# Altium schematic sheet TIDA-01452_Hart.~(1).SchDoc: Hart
size 431 x 279 mm; Date: Not shown in title block; ApprovedBy: Not shown in title block; CheckedBy: Not shown in title block; Author: Not shown in title block; CompanyName: Not shown in title block; DrawnBy: Il Han Kim; Engineer: Not shown in title block; Organization: Not shown in title block; Address1: Not shown in title block; Address2: Not shown in title block; Address3: Not shown in title block; Address4: Not shown in title block; DocumentNumber: 6; Revision: Use project parameter SCH_Rev; SheetNumber: 8; SheetTotal: 12; PageSetup: Record=PageOptions¦CenterHorizontal=True¦CenterVertical=True¦PrintScale=0.64¦XCorrection=1.00¦YCorrection=1.00¦PrintKind=0¦BorderSize=5000000¦LeftOffset=0¦BottomOffset=0¦Orientation=2¦PaperLength=1000¦PaperWidth=1000¦Scale=100¦PaperSource=15¦PrintQuality=600¦MediaType=1¦DitherType=10¦PrintScaleMode=1¦PaperKind=Letter
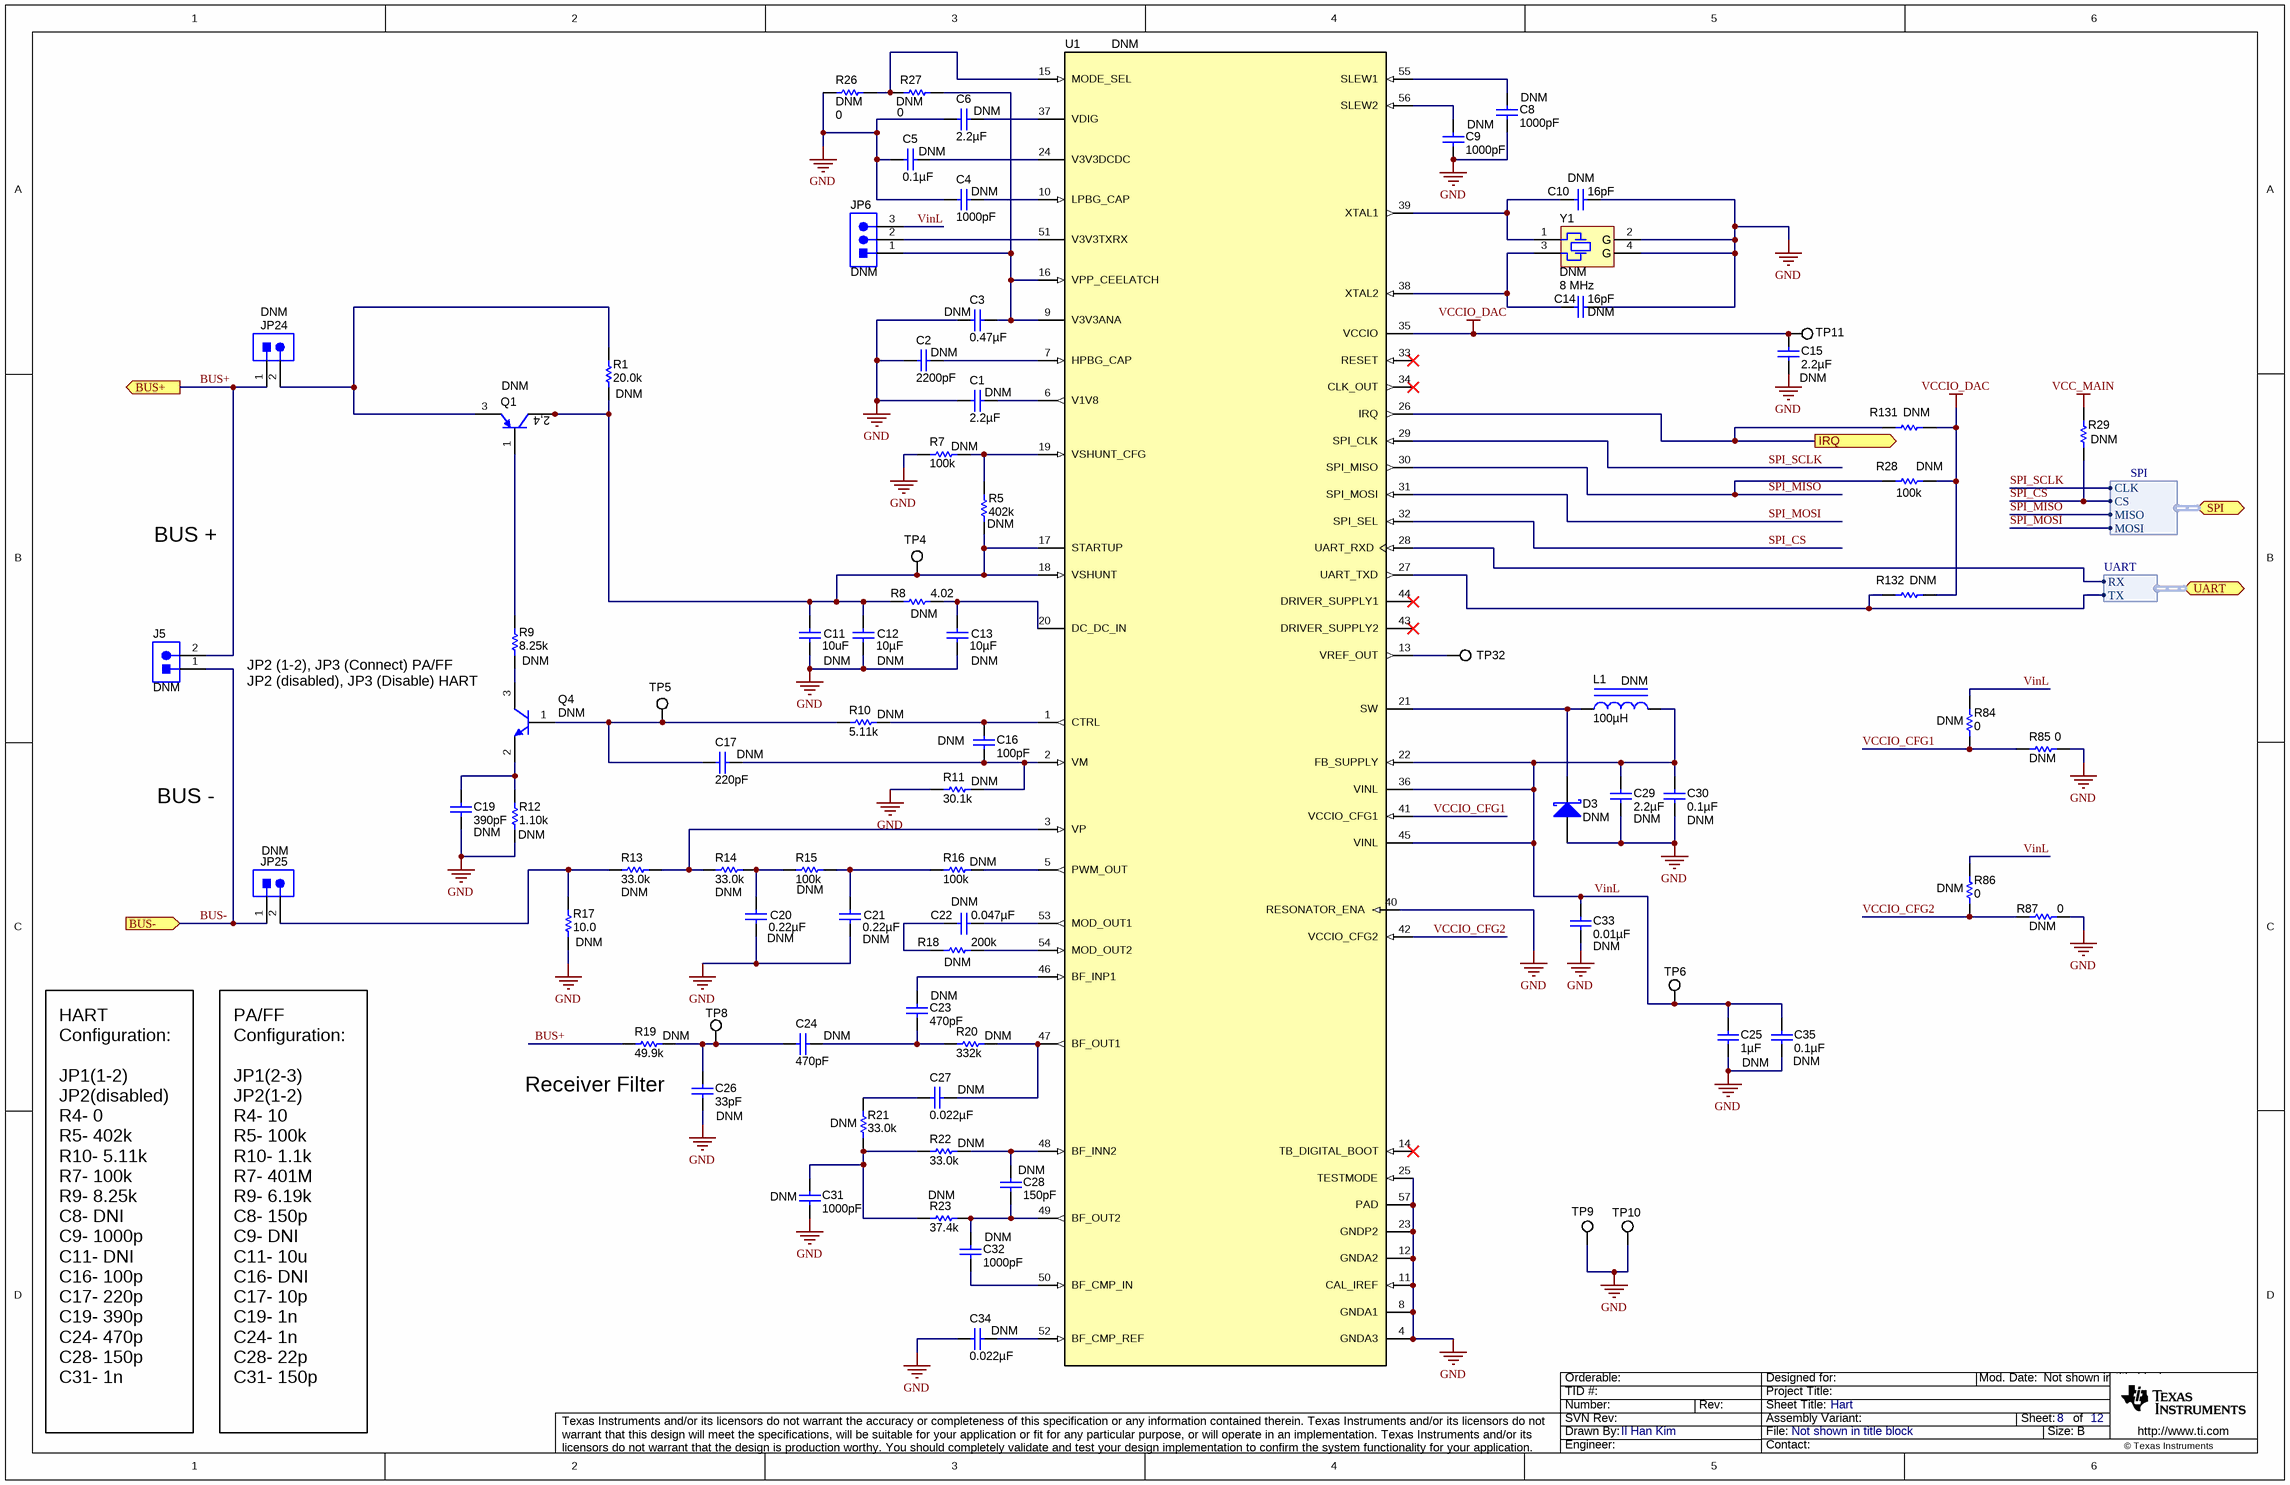
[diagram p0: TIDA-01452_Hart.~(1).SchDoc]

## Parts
C1  DNM  ValueDisplayed: 2.2µF  [0402]
C2  DNM  ValueDisplayed: 2200pF  [0402]
C3  DNM  ValueDisplayed: 0.47µF  [0402]
C4  DNM  ValueDisplayed: 1000pF  [0402]
C5  DNM  ValueDisplayed: 0.1µF  [0402]
C6  DNM  ValueDisplayed: 2.2µF  [0402]
C8  DNM  ValueDisplayed: 1000pF  [0402]
C9  DNM  ValueDisplayed: 1000pF  [0402]
C10  DNM  ValueDisplayed: 16pF  [0402]
C11  DNM  ValueDisplayed: 10uF  [1206_190]
C12  DNM  ValueDisplayed: 10µF  [1206_190]
C13  DNM  ValueDisplayed: 10µF  [1206_190]
C14  DNM  ValueDisplayed: 16pF  [0402]
C15  DNM  ValueDisplayed: 2.2µF  [0805_HV]
C16  DNM  ValueDisplayed: 100pF  [0402]
C17  DNM  ValueDisplayed: 220pF  [0402]
C19  DNM  ValueDisplayed: 390pF  [0402]
C20  DNM  ValueDisplayed: 0.22µF  [0603]
C21  DNM  ValueDisplayed: 0.22µF  [0603]
C22  DNM  ValueDisplayed: 0.047µF  [0402]
C23  DNM  ValueDisplayed: 470pF  [0402]
C24  DNM  ValueDisplayed: 470pF  [0402]
C25  DNM  ValueDisplayed: 1µF  [0402]
C26  DNM  ValueDisplayed: 33pF  [0402]
C27  DNM  ValueDisplayed: 0.022µF  [0402]
C28  DNM  ValueDisplayed: 150pF  [0402]
C29  DNM  ValueDisplayed: 2.2µF  [0805_HV]
C30  DNM  ValueDisplayed: 0.1µF  [0402]
C31  DNM  ValueDisplayed: 1000pF  [0402]
C32  DNM  ValueDisplayed: 1000pF  [0402]
C33  DNM  ValueDisplayed: 0.01µF  [0402]
C34  DNM  ValueDisplayed: 0.022µF  [0402]
C35  DNM  ValueDisplayed: 0.1µF  [0402]
D3  DNM  [sod-323]
J5  DNM  [TERM_BLK_ED555-2DS]
JP6  DNM  [CONN_TMM-103-01-T-S]
JP24  DNM  [CONN_TMM-102-01-T-S]
JP25  DNM  [CONN_TMM-102-01-T-S]
L1  DNM  ValueDisplayed: 100µH  [CBC3225]
Q1  DNM  [SOT-89-3]
Q4  DNM  [SOT-23]
R1  DNM  ValueDisplayed: 20.0k  [0603]
R5  DNM  ValueDisplayed: 402k  [0402]
R7  DNM  ValueDisplayed: 100k  [0402]
R8  DNM  ValueDisplayed: 4.02  [0603]
R9  DNM  ValueDisplayed: 8.25k  [0603]
R10  DNM  ValueDisplayed: 5.11k  [0402]
R11  DNM  ValueDisplayed: 30.1k  [0402]
R12  DNM  ValueDisplayed: 1.10k  [0603]
R13  DNM  ValueDisplayed: 33.0k  [0402]
R14  DNM  ValueDisplayed: 33.0k  [0402]
R15  DNM  ValueDisplayed: 100k  [0402]
R16  DNM  ValueDisplayed: 100k  [0402]
R17  DNM  ValueDisplayed: 10.0  [0603]
R18  DNM  ValueDisplayed: 200k  [0402]
R19  DNM  ValueDisplayed: 49.9k  [0402]
R20  DNM  ValueDisplayed: 332k  [0402]
R21  DNM  ValueDisplayed: 33.0k  [0402]
R22  DNM  ValueDisplayed: 33.0k  [0402]
R23  DNM  ValueDisplayed: 37.4k  [0402]
R26  DNM  ValueDisplayed: 0  [0402]
R27  DNM  ValueDisplayed: 0  [0402]
R28  DNM  ValueDisplayed: 100k  [0402]
R29  DNM  [0402]
R84  DNM  value 0  [0402]
R85  DNM  value 0  [0402]
R86  DNM  value 0  [0402]
R87  DNM  ValueDisplayed: 0  [0402]
R131  DNM  [0402]
R132  DNM  [0402]
TP4  NA  [TPS0.8]  (value not drawn)  (no BOM)
TP5  NA  [TPS0.8]  (value not drawn)  (no BOM)
TP6  NA  [TPS0.8]  (value not drawn)  (no BOM)
TP8  NA  [TPS0.8]  (value not drawn)  (no BOM)
TP9  NA  [TPS0.8]  (value not drawn)  (no BOM)
TP10  NA  [TPS0.8]  (value not drawn)  (no BOM)
TP11  NA  [TPS0.8]  (value not drawn)  (no BOM)
TP32  NA  [TPS0.8]  (value not drawn)  (no BOM)
U1  DNM  [DAC8730]
Y1  DNM  Frequency: 8 MHz  [XTL14S]

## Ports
BUS+ (out), BUS- (in), IRQ (out), SPI (harness SPI), UART (harness UART)

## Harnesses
SPI: CLK, CS, MISO, MOSI
UART: RX, TX

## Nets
GND: C1.2 C2.2 C3.2 C4.2 C5.2 C6.2 C8.2 C9.2 C10.1 C11.2 C12.2 C13.2 C14.1 C15.1 C19.2 C20.2 C21.2 C25.2 C26.2 C29.2 C30.2 C31.2 C33.2 C34.2 C35.2 D3.2(A) R7.2 R11.1 R12.2 R17.1 R26.2 R85.2 R87.1 TP9.1 TP10.1 U1.4(GNDA3) U1.8(GNDA1) U1.11(CAL_IREF) U1.12(GNDA2) U1.23(GNDP2) U1.25(TESTMODE) U1.40(RESONATOR_ENA) U1.57(PAD) Y1.2(GND) Y1.4(GND)
VCC_MAIN: R29.1
VCCIO_DAC: C15.2 R28.1 R131.1 R132.1 TP11.1 U1.35(VCCIO)
BUS+: J5.2 JP24.1 R19.1 ; port BUS+
BUS-: J5.1 JP25.1 ; port BUS-
IRQ: R131.2 U1.26(IRQ) ; port IRQ
SPI_CS: R29.2 U1.32(SPI_SEL) ; port SPI.CS
SPI_MISO: R28.2 U1.30(SPI_MISO) ; port SPI.MISO
SPI_MOSI: U1.31(SPI_MOSI) ; port SPI.MOSI
SPI_SCLK: U1.29(SPI_CLK) ; port SPI.CLK
VCCIO_CFG1: R84.1 R85.1 U1.41(VCCIO_CFG1)
VCCIO_CFG2: R86.1 R87.2 U1.42(VCCIO_CFG2)
VinL: C25.1 C29.1 C30.1 C33.1 C35.1 JP6.3 L1.2 R84.2 R86.2 TP6.1 U1.22(FB_SUPPLY) U1.36(VINL) U1.45(VINL)
NetC1_1: C1.1 U1.6(V1V8)
NetC2_1: C2.1 U1.7(HPBG_CAP)
NetC3_1: C3.1 JP6.1 R27.1 U1.9(V3V3ANA) U1.16(VPP_CEELATCH)
NetC4_1: C4.1 U1.10(LPBG_CAP)
NetC5_1: C5.1 U1.24(V3V3DCDC)
NetC6_1: C6.1 U1.37(VDIG)
NetC8_1: C8.1 U1.55(SLEW1)
NetC9_1: C9.1 U1.56(SLEW2)
NetC10_2: C10.2 U1.39(XTAL1) Y1.1
NetC11_1: C11.1 C12.1 Q1.2(C) Q1.4(C) R1.1 R5.1 R8.1 TP4.1 U1.17(STARTUP) U1.18(VSHUNT)
NetC13_1: C13.1 R8.2 U1.20(DC_DC_IN)
NetC14_2: C14.2 U1.38(XTAL2) Y1.3
NetC16_1: C16.1 R10.2 U1.1(CTRL)
NetC16_2: C16.2 C17.1 R11.2 U1.2(VM)
NetC17_2: C17.2 Q4.1(B) R10.1 TP5.1
NetC19_1: C19.1 Q4.2(E) R12.1
NetC20_1: C20.1 R14.2 R15.1
NetC21_1: C21.1 R15.2 R16.1
NetC22_1: C22.1 U1.53(MOD_OUT1)
NetC22_2: C22.2 R18.1
NetC23_1: C23.1 U1.46(BF_INP1)
NetC23_2: C23.2 C24.1 R20.1
NetC24_2: C24.2 C26.1 R19.2 TP8.1
NetC27_1: C27.1 R20.2 U1.47(BF_OUT1)
NetC27_2: C27.2 R21.2
NetC28_1: C28.1 R22.2 U1.48(BF_INN2)
NetC28_2: C28.2 C32.1 R23.2 U1.49(BF_OUT2)
NetC31_1: C31.1 R21.1 R22.1 R23.1
NetC32_2: C32.2 U1.50(BF_CMP_IN)
NetC34_1: C34.1 U1.52(BF_CMP_REF)
NetD3_1: D3.1(K) L1.1 U1.21(SW)
NetJP6_2: JP6.2 U1.51(V3V3TXRX)
NetJP24_2: JP24.2 Q1.3(E) R1.2
NetJP25_2: JP25.2 R13.1 R17.2
NetQ1_1: Q1.1(B) R9.2
NetQ4_3: Q4.3(C) R9.1
NetR5_2: R5.2 R7.1 U1.19(VSHUNT_CFG)
NetR13_2: R13.2 R14.1 U1.3(VP)
NetR16_2: R16.2 U1.5(PWM_OUT)
NetR18_2: R18.2 U1.54(MOD_OUT2)
NetR26_1: R26.1 R27.2 U1.15(MODE_SEL)
NetR132_2: R132.2 U1.27(UART_TXD) ; port UART.TX
NetTP32_1: TP32.1 U1.13(VREF_OUT)
NetU1_28: U1.28(UART_RXD) ; port UART.RX

Not connected (* = marked no-connect by the designer): U1 14(TB_DIGITAL_BOOT)* 33(RESET)* 34(CLK_OUT)* 43(DRIVER_SUPPLY2)* 44(DRIVER_SUPPLY1)*

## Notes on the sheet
- BUS +
- JP2 (1-2), JP3 (Connect) PA/FF
  JP2 (disabled), JP3 (Disable) HART
- BUS -
- Receiver Filter
- HART Configuration:
  JP1(1-2)
  JP2(disabled)
  R4- 0
  R5- 402k
  R10- 5.11k
  R7- 100k
  R9- 8.25k
  C8- DNI
  C9- 1000p
  C11- DNI
  C16- 100p
  C17- 220p
  C19- 390p
  C24- 470p
  C28- 150p
  C31- 1n
- PA/FF Configuration:
  JP1(2-3)
  JP2(1-2)
  R4- 10
  R5- 100k
  R10- 1.1k
  R7- 401M
  R9- 6.19k
  C8- 150p
  C9- DNI
  C11- 10u
  C16- DNI
  C17- 10p
  C19- 1n
  C24- 1n
  C28- 22p
  C31- 150p

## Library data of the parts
C1 C6 = C1005X5R1E225K050BC: CAP, CERM, 2.2 µF, 25 V, +/- 10%, X5R, 0402; Manufacturer: TDK; Polarized: N; CompType: Capacitor; Value: 2.2uF; U/M: EA; Cap_F: 0.0000022; Tolerance_%: 10; Value1: Unknown; VDC_V: 25; Value2: 25V; TaMin_C: -55; TaMax_C: 85; AEC Category: Q200
C2 = GRM155R71H222KA01D: CAP, CERM, 2200 pF, 50 V, +/- 10%, X7R, 0402; Manufacturer: MuRata; Polarized: N; CompType: Capacitor; Value: 2200pF; U/M: EA; Cap_F: 0.0000000022; Tolerance_%: 10; Value1: Unknown; VDC_V: 50; Value2: 50V; TaMin_C: -55; TaMax_C: 125; AEC Category: Q200
C3 = GRM155R61C474KE01: CAP, CERM, 0.47 µF, 16 V, +/- 10%, X5R, 0402; Manufacturer: MuRata; Polarized: N; CompType: Capacitor; Value: 0.47uF; U/M: EA; Cap_F: 0.00000047; Tolerance_%: 10; Value1: Unknown; VDC_V: 16; Value2: 16V; TaMin_C: -55; TaMax_C: 85; AEC Category: Q200
C4 C8 C9 C31 C32 = GRM1555C1H102JA01D: CAP, CERM, 1000 pF, 50 V, +/- 5%, C0G/NP0, 0402; Manufacturer: MuRata; Polarized: N; CompType: Capacitor; Value: 1000pF; U/M: EA; Cap_F: 0.000000001; Tolerance_%: 5; Value1: Unknown; VDC_V: 50; Value2: 50V; TaMin_C: -55; TaMax_C: 125; AEC Category: Q200
C5 C30 C35 = GCM155R71H104KE02D: CAP, CERM, 0.1 µF, 50 V, +/- 10%, X7R, AEC-Q200 Grade 1, 0402; Manufacturer: MuRata; Polarized: N; CompType: Capacitor; Value: 0.1uF; U/M: EA; Cap_F: 0.0000001; Tolerance_%: 10; Value1: Unknown; VDC_V: 50; Value2: 50V; TaMin_C: -55; TaMax_C: 125; AEC Category: Q200; AEC Qualified: Y; AEC Grade: 1
C10 C14 = GRM1555C1H160JA01D: CAP, CERM, 16 pF, 50 V, +/- 5%, C0G/NP0, 0402; Manufacturer: MuRata; Polarized: N; CompType: Capacitor; Value: 16pF; U/M: EA; Cap_F: 0.000000000016; Tolerance_%: 5; Value1: Unknown; VDC_V: 50; Value2: 50V; TaMin_C: -55; TaMax_C: 125; SizeArea_mm2: 0.5; SizeAreaWB_mm2: 3; SizeX_mm: 1; SizeZ_mm: 0.6; AEC Category: Q200
C11 = C1206C106K3RACTU: Cap Cerm. MLCC 10uF 25 Volts 10% X7R 1206; Manufacturer: Kemet; Polarized: N; CompType: Capacitor; U/M: EA; Cap_F: 0.00001; Tolerance_%: 10; Value1: Unknown; VDC_V: 25; Value2: 25V; TaMin_C: -55; TaMax_C: 125; Cap_Case: 1206; AEC Category: Q200
C12 C13 = C1206C106K3RACTU: CAP, CERM, 10 µF, 25 V, +/- 10%, X7R, 1206_190; Manufacturer: Kemet; Polarized: N; CompType: Capacitor; Value: 10uF; U/M: EA; Cap_F: 0.00001; Tolerance_%: 10; Value1: Unknown; VDC_V: 25; Value2: 25V; TaMin_C: -55; TaMax_C: 125; Cap_Case: 1206; AEC Category: Q200
C15 C29 = C0805C225K4RACTU: CAP, CERM, 2.2 µF, 16 V, +/- 10%, X7R, 0805; Manufacturer: Kemet; Polarized: N; CompType: Capacitor; Value: 2.2uF; U/M: EA; Cap_F: 0.0000022; Tolerance_%: 10; ESR_ohm: 0.008; Value1: 0.008 ohm; VDC_V: 16; Value2: 16V; IRMS_A: 15.55; TaMin_C: -55; TaMax_C: 125; Cap_Case: 0805; AEC Category: Q200
C16 = GRM1535C1H101JDD5D: CAP, CERM, 100 pF, 50 V, +/- 5%, C0G/NP0, 0402; Manufacturer: MuRata; Polarized: N; CompType: Capacitor; Value: 100pF; U/M: EA; Cap_F: 0.0000000001; Tolerance_%: 5; Value1: Unknown; VDC_V: 50; Value2: 50V; TaMin_C: -55; TaMax_C: 125; AEC Category: Q200
C17 = GRM1555C1H221JA01D: CAP, CERM, 220 pF, 50 V, +/- 5%, C0G/NP0, 0402; Manufacturer: MuRata; Polarized: N; CompType: Capacitor; Value: 220pF; U/M: EA; Cap_F: 0.00000000022; Tolerance_%: 5; Value1: Unknown; VDC_V: 50; Value2: 50V; TaMin_C: -55; TaMax_C: 125; AEC Category: Q200
C19 = GRM1555C1H391JA01D: CAP, CERM, 390 pF, 50 V, +/- 5%, C0G/NP0, 0402; Manufacturer: MuRata; Polarized: N; CompType: Capacitor; Value: 390pF; U/M: EA; Cap_F: 0.00000000039; Tolerance_%: 5; Value1: Unknown; VDC_V: 50; Value2: 50V; TaMin_C: -55; TaMax_C: 125; AEC Category: Q200
C20 C21 = 885012206048: CAP, CERM, 0.22 µF, 16 V, +/- 10%, X7R, 0603; Manufacturer: Wurth Elektronik; Polarized: N; CompType: Capacitor; Value: 0.22uF; U/M: EA; Cap_F: 0.00000022; Tolerance_%: 10; Value1: Unknown; VDC_V: 16; Value2: 16V; TaMin_C: -55; TaMax_C: 125; AEC Category: Q200
C22 = C1005X7R1H473K050BB: CAP, CERM, 0.047 µF, 50 V, +/- 10%, X7R, 0402; Manufacturer: TDK; Polarized: N; CompType: Capacitor; Value: 0.047uF; U/M: EA; Cap_F: 0.000000047; Tolerance_%: 10; Value1: Unknown; VDC_V: 50; Value2: 50V; TaMin_C: -55; TaMax_C: 125; AEC Category: Q200
C23 C24 = GRM1555C1H471JA01D: CAP, CERM, 470 pF, 50 V, +/- 5%, C0G/NP0, 0402; Manufacturer: MuRata; Polarized: N; CompType: Capacitor; Value: 470pF; U/M: EA; Cap_F: 0.00000000047; Tolerance_%: 5; Value1: Unknown; VDC_V: 50; Value2: 50V; TaMin_C: -55; TaMax_C: 125; AEC Category: Q200
C25 = GRM155R61E105KA12D: CAP, CERM, 1 µF, 25 V, +/- 10%, X5R, 0402; Manufacturer: MuRata; Polarized: N; CompType: Capacitor; Value: 1uF; U/M: EA; Cap_F: 0.000001; Tolerance_%: 10; Value1: Unknown; VDC_V: 25; Value2: 25V; TaMin_C: -55; TaMax_C: 85; AEC Category: Q200
C26 = GRM1555C1H330JA01D: CAP, CERM, 33 pF, 50 V, +/- 5%, C0G/NP0, 0402; Manufacturer: MuRata; Polarized: N; CompType: Capacitor; Value: 33pF; U/M: EA; Cap_F: 0.000000000033; Tolerance_%: 5; Value1: Unknown; VDC_V: 50; Value2: 50V; TaMin_C: -55; TaMax_C: 125; AEC Category: Q200
C27 C34 = GCM155R71H223KA55D: CAP, CERM, 0.022 µF, 50 V, +/- 10%, C0G/NP0, 0402; Manufacturer: MuRata; Polarized: N; CompType: Capacitor; Value: 0.022uF; U/M: EA; Cap_F: 0.000000022; Tolerance_%: 10; Value1: Unknown; VDC_V: 50; Value2: 50V; TaMin_C: -55; TaMax_C: 125; AEC Category: Q200
C28 = GRM1555C1H151JA01D: CAP, CERM, 150 pF, 50 V, +/- 5%, C0G/NP0, 0402; Manufacturer: MuRata; Polarized: N; CompType: Capacitor; Value: 150pF; U/M: EA; Cap_F: 0.00000000015; Tolerance_%: 5; Value1: Unknown; VDC_V: 50; Value2: 50V; TaMin_C: -55; TaMax_C: 125; AEC Category: Q200
C33 = GCM155R71H103KA55D: CAP, CERM, 0.01 µF, 50 V, +/- 10%, C0G/NP0, 0402; Manufacturer: MuRata; Polarized: N; CompType: Capacitor; Value: 0.01uF; U/M: EA; Cap_F: 0.00000001; Tolerance_%: 10; Value1: Unknown; VDC_V: 50; Value2: 50V; TaMin_C: -55; TaMax_C: 125; AEC Category: Q200
D3 = BAT54WS-7-F: Diode, Schottky, 30 V, 0.2 A, SOD-323; Manufacturer: Diodes Inc.; U/M: EA; Vf_V: 0.7; Value: 30V; Value1: 0.2A; Value2: 0.7V; Io_A: 0.2; Vr_V: 30; TJmax_C: 125; AEC Category: Q101
J5 = ED555/2DS: Terminal Block, 6A, 3.5mm Pitch, 2-Pos, TH; Manufacturer: On-Shore Technology; SymbolCreator: a0412235; CompType: Connector; U/M: EA
JP6 = TMM-103-01-T-S: Header, 2mm, 3x1, Tin, TH; Manufacturer: Samtec; SymbolCreator: a0799628; U/M: EA
JP24 JP25 = TMM-102-01-T-S: Header, 2mm, 2x1, Tin, TH; Manufacturer: Samtec; SymbolCreator: a0412235; U/M: EA
L1 = CBC3225T101MR: Inductor, Wirewound, 100 µH, 0.27 A, 1.4 ohm, SMD; Manufacturer: Taiyo Yuden; Value: 100uH; Ind_H: 100.0E-6; Imax_A: 0.27; Irms: 0.34A @ 40C rise; Isat: 0.27A @ 30% inductance drop; DCR_ohm: 1.4; Value1: 1.4 ohm; Value2: 0.27A; AEC Category: Q200; AEC Qualified: N
Q1 = 2SB1260T100R, Rohm: Transistor, PNP, 80 V, 1 A, SOT-89; Manufacturer: Rohm; CompType: BJT; PNP: 1; NPN: 0; Vceo_V: 80; Vcesat1_V: 0.4; Value: 80 V; Value1: 1 A; HfeMax: 390; TaMin_C: -55; TaMax_C: 150; U/M: EA; AEC Category: Q101
Q4 = BC846BLT1G, ON Semiconductor: Transistor, NPN, 65 V, 0.1 A, SOT-23; CompType: BJT; PNP: 0; NPN: 1; Vceo_V: 65; Vcesat1_V: 0.7; Value: 65 V; IcRated_A: 0.1; Value1: 0.1 A; HfeMax: 450; TaMin_C: -55; TaMax_C: 150; U/M: EA; AEC Category: Q101
R1 = RC0603FR-0720KL: RES, 20.0 k, 1%, 0.1 W, 0603; Manufacturer: Yageo America; CompType: Resistor; Value: 20.0k; Res_ohm: 20000; Value_Code: 20k0; Tolerance_%: 1; Power_W: 0.1; Value2: 0.1W; VDC_V: 150; TempCo: 200 ppm/C; EIA_Code: E96; U/M: EA; AEC Category: Q200
R5 = CRCW0402402KFKED: RES, 402 k, 1%, 0.063 W, 0402; Manufacturer: Vishay-Dale; CompType: Resistor; Value: 402k; Res_ohm: 402000; Tolerance_%: 1; Power_W: 0.063; Value2: 0.063W; VDC_V: 50; TempCo: 100 ppm/C; EIA_Code: E96; U/M: EA; AEC Category: Q200
R7 R15 R16 R28 R29 R131 R132 = CRCW0402100KFKED: RES, 100 k, 1%, 0.063 W, 0402; Manufacturer: Vishay-Dale; CompType: Resistor; Value: 100k; Res_ohm: 100000; Tolerance_%: 1; Power_W: 0.063; Value2: 0.063W; VDC_V: 50; TempCo: 100 ppm/C; EIA_Code: E96; U/M: EA; AEC Category: Q200
R8 = CRCW06034R02FKEA: RES, 4.02, 1%, 0.1 W, 0603; Manufacturer: Vishay-Dale; CompType: Resistor; Value: 4.02; Value_Code: 4R02; Tolerance_%: 1; Power_W: 0.1; Value2: 0.1W; VDC_V: 75; TempCo: 100 ppm/C; EIA_Code: E96; U/M: EA; AEC Category: Q200
R9 = CRCW06038K25FKEA: RES, 8.25 k, 1%, 0.1 W, 0603; Manufacturer: Vishay-Dale; CompType: Resistor; Value: 8.25k; Res_ohm: 8250; Value_Code: 8k25; Tolerance_%: 1; Power_W: 0.1; Value2: 0.1W; VDC_V: 75; TempCo: 100 ppm/C; EIA_Code: E96; U/M: EA; AEC Category: Q200
R10 = CRCW04025K11FKED: RES, 5.11 k, 1%, 0.063 W, 0402; Manufacturer: Vishay-Dale; CompType: Resistor; Value: 5.11k; Res_ohm: 5110; Value_Code: 5k11; Tolerance_%: 1; Power_W: 0.063; Value2: 0.063W; VDC_V: 50; TempCo: 100 ppm/C; EIA_Code: E96; U/M: EA; AEC Category: Q200
R11 = CRCW040230K1FKED: RES, 30.1 k, 1%, 0.063 W, 0402; Manufacturer: Vishay-Dale; CompType: Resistor; Value: 30.1k; Res_ohm: 30100; Value_Code: 30k1; Tolerance_%: 1; Power_W: 0.063; Value2: 0.063W; VDC_V: 50; TempCo: 100 ppm/C; EIA_Code: E96; U/M: EA; AEC Category: Q200
R12 = CRCW06031K10FKEA: RES, 1.10 k, 1%, 0.1 W, 0603; Manufacturer: Vishay-Dale; CompType: Resistor; Value: 1.10k; Res_ohm: 1100; Value_Code: 1k10; Tolerance_%: 1; Power_W: 0.1; Value2: 0.1W; VDC_V: 75; TempCo: 100 ppm/C; EIA_Code: E96; U/M: EA; AEC Category: Q200
R13 R14 R21 R22 = ERA-2AEB333X: RES, 33.0 k, 0.1%, 0.063 W, 0402; Manufacturer: Panasonic; CompType: Resistor; Value: 33.0k; Res_ohm: 33000; Value_Code: 33k0; Tolerance_%: 0.1; Power_W: 0.063; Value2: 0.063W; VDC_V: 50; TempCo: 25 ppm/C; U/M: EA; AEC Category: Q200
R17 = CRCW060310R0FKEA: RES, 10.0, 1%, 0.1 W, 0603; Manufacturer: Vishay-Dale; CompType: Resistor; Value: 10.0; Res_ohm: 10; Value_Code: 10R0; Tolerance_%: 1; Power_W: 0.1; Value2: 0.1W; VDC_V: 75; TempCo: 100 ppm/C; EIA_Code: E96; U/M: EA; AEC Category: Q200
R18 = CRCW0402200KFKED: RES, 200 k, 1%, 0.063 W, 0402; Manufacturer: Vishay-Dale; CompType: Resistor; Value: 200k; Res_ohm: 200000; Tolerance_%: 1; Power_W: 0.063; Value2: 0.063W; VDC_V: 50; TempCo: 100 ppm/C; EIA_Code: E96; U/M: EA; AEC Category: Q200
R19 = CRCW040249K9FKED: RES, 49.9 k, 1%, 0.063 W, 0402; Manufacturer: Vishay-Dale; CompType: Resistor; Value: 49.9k; Res_ohm: 49900; Value_Code: 49k9; Tolerance_%: 1; Power_W: 0.063; Value2: 0.063W; VDC_V: 50; TempCo: 100 ppm/C; EIA_Code: E96; U/M: EA; AEC Category: Q200
R20 = CRCW0402332KFKED: RES, 332 k, 1%, 0.063 W, 0402; Manufacturer: Vishay-Dale; CompType: Resistor; Value: 332k; Res_ohm: 332000; Tolerance_%: 1; Power_W: 0.063; Value2: 0.063W; VDC_V: 50; TempCo: 100 ppm/C; EIA_Code: E96; U/M: EA; AEC Category: Q200
R23 = CRCW040237K4FKED: RES, 37.4 k, 1%, 0.063 W, 0402; Manufacturer: Vishay-Dale; CompType: Resistor; Value: 37.4k; Res_ohm: 37400; Value_Code: 37k4; Tolerance_%: 1; Power_W: 0.063; Value2: 0.063W; VDC_V: 50; TempCo: 100 ppm/C; EIA_Code: E96; U/M: EA; AEC Category: Q200
R26 = CRCW04020000Z0ED: RES, 0, 5%, 0.063 W, 0402; Manufacturer: Vishay-Dale; CompType: Resistor; Value: 0; Value_Code: 0000; Tolerance_%: 5; Power_W: 0.063; Value2: 0.063W; VDC_V: 50; TempCo: 200 ppm/C; EIA_Code: E24; U/M: EA; AEC Category: Q200
R27 R87 = CRCW04020000Z0ED: RES, 0, 5%, 0.063 W, 0402; Manufacturer: Vishay-Dale; CompType: Resistor; Value: 0; Value_Code: 0000; Tolerance_%: 5; Power_W: 0.063; Value2: 0.063W; VDC_V: 50; TempCo: 200 ppm/C; EIA_Code: E24; U/M: EA
R84-R86 = CRCW04020000Z0ED: RES, 0, 5%, 0.063 W, 0402; Manufacturer: Vishay-Dale; CompType: Resistor; Value_Code: 0000; Tolerance_%: 5; Power_W: 0.063; Value2: 0.063W; VDC_V: 50; TempCo: 200 ppm/C; EIA_Code: E24; U/M: EA
TP4-TP6 TP8-TP11 TP32 = TEST_POINT_ROUND_1.2: Round Test Point, 1.2mm diam.
U1 = DAC8730: DAC8730, DAC8730; Manufacturer: Texas Instruments; SymbolCreator: Altium; CompType: IC; U/M: EA
Y1 = ABM3B-8.000MHZ-10-1-U-T: Crystal, 8 MHz, 10 pF, SMD; Manufacturer: Abracon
